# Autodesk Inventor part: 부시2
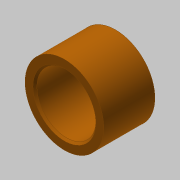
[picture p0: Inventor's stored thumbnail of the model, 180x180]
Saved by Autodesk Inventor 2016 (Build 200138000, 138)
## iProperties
Created: 2016-08
Part Number: 부시2
Material: 강철, 탄소
Document SubType Name: Modeling
Designer: mduedu
Density: 7.87 g/cm^3
Appearance: 주황색
Author: mduedu
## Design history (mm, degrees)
sketch "스케치1"
  geometry: C1 r 7.5 at (0, 0); C2 r 10 at (0, 0); 1 further point
  constraints: 2 centre point, 2 coincident
  dimensions: "d0" = 15 diameter of C1; "d1" = 20 diameter of C2
extrude "돌출1" new body sketch "스케치1" stored distance "d2" = 13; taper "d3" = 0 deg
chamfer "모따기1" distance "d4" = 0.5; stored, may be unused: second distance "d5" = 2, angle "d6" = 45 deg
node "솔리드1"
